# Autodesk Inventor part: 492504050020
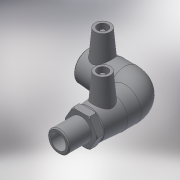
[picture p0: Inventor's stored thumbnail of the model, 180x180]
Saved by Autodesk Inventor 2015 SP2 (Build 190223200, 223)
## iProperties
Created: 2017-06
Part Number: 492504050020
Material: Generic
Description: PLASSON 90° ELBOW MALE TRANSITION 50-2"
Document SubType Name: Modeling
Designer: KIM
Mass: 323.118 g
Surface Area: 715.657 cm^2
Volume: 323.118 cm^3
Density: 1 g/cm^3
Appearance: Default
Author: KIM
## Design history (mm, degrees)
derived "492504.ipt"
feature "Solid1::492504.ipt"
tag "TaggingFeature1"
body "Solid1"
other parameters: "d2" = 67, "d4" = 36, "d5" = 60.3, "d8" = 168 deg, "d10" = 19.2, "d11" = 6.4, "d29" = 52, "d30" = 15, "d31" = 59.4, "d34" = 5 deg, "d41" = 4, "d42" = 14, "d43" = 0, "d48" = 74.5, "d50" = 42.5, "d51" = 19.2, "d52" = 48, "d54" = 90 deg, "d58" = 48, "d59" = 0, "d61" = 90 deg, "d86" = 3, "d87" = 0, "d93" = 0.1, "d94" = 10.25, "d95" = 59.614, "d96" = 41.7298, "d97" = 38, "d98" = 41, "d99" = 73.7, "d100" = 36.9, "d102" = 2.5, "d106" = 0, "L_" = 149, "L_1" = 48, "D_" = 38, "A_" = 52, "d_2" = 12, "L_2" = 41, "D_1" = 67, "R_" = 59.614
